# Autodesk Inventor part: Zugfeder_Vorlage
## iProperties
Shininess: 20.0
Length Units: 11269
Angle Units: 11279
Time Units: 11290
Mass Units: 11283
Length Display Precision: 3
Angle Display Precision: 2
Part Number: Zugfeder_Vorlage
Material: Stahl (hohe Festigkeit, niedrige Legierung)
Document SubType Name: Modellieren
Created: 2003-03
Designer: swi
Description: Zugfeder
Density: 0.0
Volumn: 0.0
Area: 0.0
PropertySet Name: Model Information
Control State: 0
Master: False
Checked Out: False
Author: swi
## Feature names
1. Spirale1
2. Sweeping1
3. Sweeping2
4. Runde Anordnung1 [Circular Pattern]
